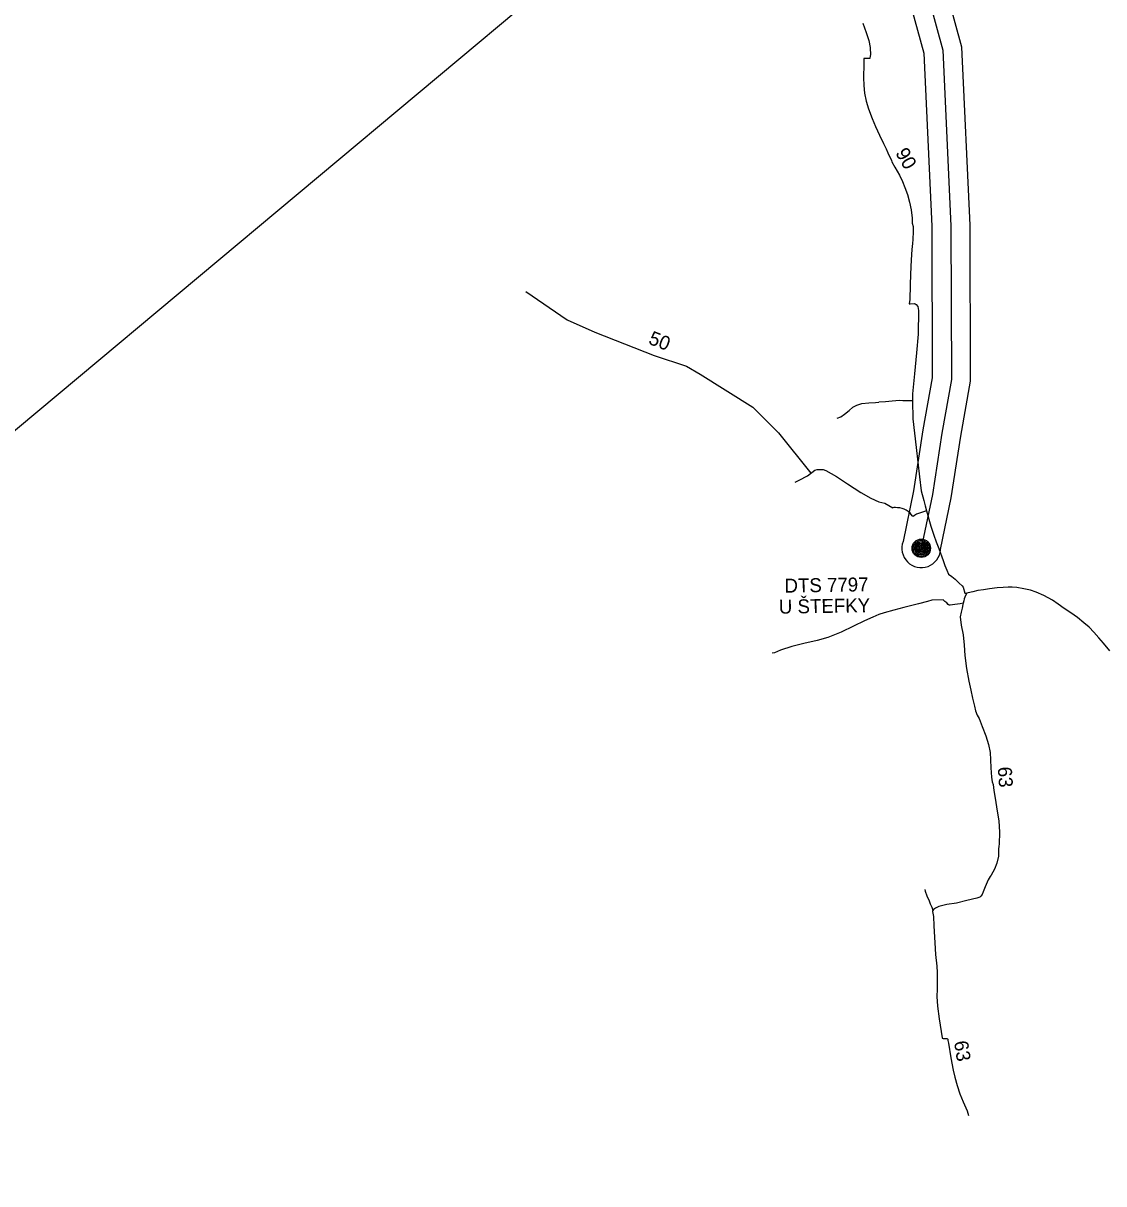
# Model space of a CAD drawing. Extents: x -444841 to -429545, y -1135312 to -1129851.
# Drawn here: x -443164 to -442545, y -1132368 to -1131703 of the extents above; entities that cross this region are included whole.
import ezdxf

# ---------------------------------------------------------------- set-up
doc = ezdxf.new("R2010")
doc.units = 0
for name, color, linetype in [('Vrstva 10', 7, 'Continuous'), ('Vrstva 11', 7, 'Continuous'), ('Vrstva 13', 7, 'Continuous'), ('Vrstva 15', 7, 'Continuous'), ('Vrstva 27', 7, 'Continuous'), ('Vrstva 30', 7, 'Continuous'), ('Vrstva 35', 7, 'Continuous'), ('Vrstva 38', 7, 'Continuous'), ('Vrstva 59', 7, 'Continuous')]:
    doc.layers.add(name, color=color, linetype=linetype)

msp = doc.modelspace()

# ---------------------------------------------------------------- linework, layer by layer
at = {"layer": 'Vrstva 10'}
msp.add_lwpolyline([(-442977.06, -1131273.28), (-442915.98, -1131331.48), (-442844.48, -1131404.21), (-442778.35, -1131472.42), (-442708.6, -1131543.25), (-442667.15, -1131610.03), (-442637.47, -1131718.34), (-442632.84, -1131818.91), (-442632.55, -1131906.97), (-442638.07, -1131937.77), (-442643.43, -1131972.89), (-442649.82, -1132003.75)], dxfattribs=at)
at = {"layer": 'Vrstva 11'}
for radius in [5.25, 4.55, 3.85, 3.15, 2.45, 1.75, 1.05, 0.35]:
    msp.add_circle((-442649.82, -1132003.75), radius, dxfattribs=at)
at = {"layer": 'Vrstva 15'}
for points in [[(-442638.75, -1132004.52), (-442632.6, -1131974.83), (-442627.22, -1131939.57), (-442621.55, -1131907.93), (-442621.84, -1131818.64), (-442626.54, -1131716.61), (-442656.97, -1131605.59), (-442699.9, -1131536.41), (-442770.48, -1131464.73), (-442836.6, -1131396.52), (-442908.26, -1131323.64), (-442958.88, -1131275.41)], [(-442977.76, -1131287.8), (-442923.69, -1131339.31), (-442852.35, -1131411.89), (-442786.22, -1131480.11), (-442717.3, -1131550.09), (-442677.34, -1131614.48), (-442648.4, -1131720.07), (-442643.84, -1131819.18), (-442643.56, -1131906.01), (-442648.92, -1131935.97), (-442654.27, -1131970.94), (-442660.2, -1131999.82)]]:
    msp.add_lwpolyline(points, dxfattribs=at)
msp.add_arc((-442649.82, -1132003.75), 11.1, 159.24982, 356.0105, dxfattribs=at)
at = {"layer": 'Vrstva 27'}
for points in [[(-442683.26, -1131702.79), (-442681.33, -1131708.2), (-442679.93, -1131712.74), (-442679.16, -1131716.75), (-442678.98, -1131721.16), (-442679.04, -1131721.49), (-442679.23, -1131723.11), (-442679.72, -1131723.11), (-442682.33, -1131723.08), (-442682.76, -1131723.14), (-442682.81, -1131727.48), (-442682.92, -1131732.83), (-442682.99, -1131733.98), (-442682.76, -1131738.59), (-442682.37, -1131742.94), (-442681.45, -1131747.48), (-442680.13, -1131751.94), (-442677.92, -1131757.48), (-442675.94, -1131762.15), (-442673.78, -1131766.98), (-442671.47, -1131771.89), (-442669.9, -1131774.96), (-442669, -1131777.08), (-442666.96, -1131781.5), (-442666.58, -1131782.26), (-442664.96, -1131785.47), (-442662.35, -1131789.93), (-442660.55, -1131793.61), (-442659.13, -1131796.94), (-442657.73, -1131801.12), (-442656.47, -1131805.53), (-442655.65, -1131809.8), (-442654.99, -1131814.57), (-442654.96, -1131817.48), (-442654.5, -1131819.47), (-442654.53, -1131822.31), (-442654.63, -1131826.82), (-442654.91, -1131829.09), (-442655.2, -1131832.5), (-442655.63, -1131838.52), (-442656.06, -1131846.7), (-442656.25, -1131852.95), (-442656.4, -1131861.27), (-442656.68, -1131863.73), (-442656.22, -1131863.72), (-442653.68, -1131863.56), (-442653.22, -1131863.67), (-442652.77, -1131864.06), (-442651.69, -1131865.23), (-442651.46, -1131867.54), (-442651.66, -1131881.03), (-442652.52, -1131891.73), (-442653.62, -1131903.77), (-442654.78, -1131915.3), (-442654.74, -1131919.22)], [(-442698.06, -1131929.23), (-442695.98, -1131928.4), (-442693.71, -1131926.88), (-442691.15, -1131924.8), (-442689.1, -1131922.92), (-442686.72, -1131921.67), (-442683.95, -1131920.76), (-442679.82, -1131920.37), (-442676.09, -1131920.27), (-442674.05, -1131920.13)], [(-442654.74, -1131919.22), (-442660.28, -1131919.2), (-442662.22, -1131919.17), (-442666.51, -1131919.48), (-442670.39, -1131919.87), (-442674.05, -1131920.13)], [(-442654.74, -1131919.22), (-442654.63, -1131929.58), (-442652.79, -1131946.11), (-442650.81, -1131962.76), (-442649.87, -1131970.86), (-442648.43, -1131976.41), (-442647.64, -1131979.49), (-442646.88, -1131982.38)], [(-442722, -1131965.95), (-442719.7, -1131964.73), (-442715.06, -1131962.27), (-442710.74, -1131958.98), (-442709.46, -1131958.66), (-442708.17, -1131958.54), (-442706.08, -1131958.67), (-442704.41, -1131959.25), (-442698.34, -1131962.72), (-442692.03, -1131966.75), (-442684.44, -1131971.71), (-442678.78, -1131975.11), (-442674.17, -1131977.14), (-442670.78, -1131977.87), (-442666.08, -1131980.59)], [(-442646.88, -1131982.38), (-442648.03, -1131982.66), (-442652.48, -1131984.22), (-442653.73, -1131984.96), (-442654.39, -1131985.48), (-442654.73, -1131985.4), (-442654.98, -1131985.1), (-442656.07, -1131983.91), (-442657.28, -1131982.65), (-442657.8, -1131982.3), (-442658.49, -1131981.9), (-442659.62, -1131981.43), (-442660.68, -1131980.9), (-442662.07, -1131980.66), (-442663.36, -1131980.52), (-442664.59, -1131980.46), (-442665.44, -1131980.46), (-442666.08, -1131980.59)], [(-442646.88, -1131982.38), (-442644.38, -1131991.12), (-442642.6, -1131996.33), (-442641.26, -1132000)], [(-442641.26, -1132000), (-442639.81, -1132003.98), (-442637.34, -1132010.82), (-442636.35, -1132013.66), (-442635.21, -1132016.3), (-442634.11, -1132018.53), (-442632.23, -1132019.94), (-442630.33, -1132021.55), (-442628, -1132023.81), (-442626.42, -1132025.2), (-442625.79, -1132026.04), (-442624.86, -1132029.46), (-442623.65, -1132029.44)], [(-442541.82, -1132062.57), (-442545.37, -1132058.16), (-442547.99, -1132055.08), (-442550.86, -1132051.8), (-442553.63, -1132049.05), (-442556.58, -1132046.46), (-442560.24, -1132043.5), (-442564.18, -1132040.75), (-442567.88, -1132038.25), (-442571.3, -1132035.8), (-442574.64, -1132033.55), (-442579.47, -1132030.9), (-442584, -1132028.88), (-442587.25, -1132027.83), (-442590.94, -1132026.94), (-442594.96, -1132026.31), (-442597.7, -1132026.1), (-442600.01, -1132025.96), (-442602.78, -1132026.32), (-442606.4, -1132026.51), (-442610.67, -1132027.06), (-442614.18, -1132027.62), (-442617.46, -1132028.05), (-442620.31, -1132028.72), (-442622.86, -1132029.24), (-442623.65, -1132029.44)], [(-442625.77, -1132035.29), (-442627.53, -1132035.66), (-442630.57, -1132036.07), (-442633.26, -1132036.43), (-442633.86, -1132036.38), (-442634.42, -1132036.06), (-442635.21, -1132034.98), (-442636.26, -1132034.2), (-442637.3, -1132033.25), (-442643.68, -1132033.56), (-442646.23, -1132034.22), (-442651.44, -1132035.61), (-442659.78, -1132037.74), (-442665.61, -1132039.32), (-442671.05, -1132040.66)], [(-442625.77, -1132035.29), (-442625.93, -1132036.04), (-442626.39, -1132038.05), (-442627.01, -1132040.31), (-442627.48, -1132043.06), (-442626.97, -1132047.91), (-442625.88, -1132053.42), (-442625.28, -1132059.22), (-442624.84, -1132065.27), (-442623.92, -1132072.58), (-442622.58, -1132080), (-442621.47, -1132085.06), (-442620.47, -1132089.63), (-442619.29, -1132094.27), (-442618.7, -1132096.98), (-442617.85, -1132099.45), (-442616.69, -1132101.36), (-442614.86, -1132105.84), (-442612.76, -1132111.32), (-442611.31, -1132116.14), (-442610.29, -1132120.69), (-442610.16, -1132124.96), (-442609.85, -1132129.62), (-442609.51, -1132134.86), (-442609.08, -1132137.55), (-442608.55, -1132139.14), (-442608.2, -1132142.61), (-442607.29, -1132148.15), (-442606.46, -1132153.25), (-442605.33, -1132159.95), (-442604.93, -1132166.37), (-442605.1, -1132173.36), (-442605.28, -1132174.53), (-442605.54, -1132176.17), (-442605.46, -1132177.95), (-442605.51, -1132180.25), (-442606.52, -1132184.11), (-442607.88, -1132187.57), (-442609.82, -1132191.03), (-442610.37, -1132191.83), (-442611.49, -1132193.82), (-442613.11, -1132197.7), (-442614.24, -1132200.67), (-442614.88, -1132202.15), (-442615.59, -1132203.15), (-442616.21, -1132203.72), (-442617.96, -1132204.17), (-442623.75, -1132205.54), (-442629.56, -1132207.04), (-442635.08, -1132207.86), (-442639.69, -1132209.08), (-442641.65, -1132209.94), (-442642.76, -1132210.74), (-442643.16, -1132211.29)], [(-442623.65, -1132029.44), (-442624.37, -1132030.91), (-442625.18, -1132032.69), (-442625.46, -1132033.89), (-442625.77, -1132035.29)], [(-442671.05, -1132040.66), (-442674.2, -1132041.7), (-442677.62, -1132043.15), (-442682.35, -1132045.4), (-442688.71, -1132048.44), (-442695.74, -1132051.81), (-442703.28, -1132054.87), (-442709.43, -1132056.59), (-442717.16, -1132058.28), (-442724.03, -1132059.96), (-442730.53, -1132062.13), (-442733.93, -1132063.61), (-442735.19, -1132063.8)], [(-442647.78, -1132199.24), (-442647.48, -1132200.22), (-442646.59, -1132202.97), (-442645.22, -1132205.82), (-442644.71, -1132207.56), (-442643.83, -1132209.39), (-442643.16, -1132211.29)], [(-442643.16, -1132211.29), (-442643.28, -1132211.88), (-442643.22, -1132212.94), (-442642.78, -1132214.75), (-442642.59, -1132220.1), (-442642.06, -1132229.81), (-442641.6, -1132236.62), (-442640.98, -1132243.29), (-442640.75, -1132246.78), (-442640.67, -1132256.31), (-442640.82, -1132260.57), (-442640.59, -1132266.21), (-442639.57, -1132273.37), (-442638.99, -1132277.01), (-442637.79, -1132284.19), (-442637.74, -1132284.49), (-442637.34, -1132284.72), (-442635.07, -1132284.6), (-442634.8, -1132284.77), (-442634.64, -1132285.12), (-442634.54, -1132285.82), (-442634.12, -1132287.34), (-442632.78, -1132295.82), (-442631.59, -1132302.83), (-442630.58, -1132306.85), (-442629.2, -1132311.68), (-442627.63, -1132316.45), (-442625.87, -1132320.94), (-442623.53, -1132326.18), (-442622.71, -1132328.71)]]:
    msp.add_lwpolyline(points, dxfattribs=at)
at = {"layer": 'Vrstva 35'}
msp.add_lwpolyline([(-442876.35, -1131856.53), (-442852.67, -1131872.82), (-442836.97, -1131879.92), (-442802.93, -1131893.25), (-442784.27, -1131899.46), (-442776.58, -1131903.91), (-442746.38, -1131922.85), (-442731.57, -1131937.66), (-442713.13, -1131960.8)], dxfattribs=at)
at = {"layer": 'Vrstva 59'}
msp.add_lwpolyline([(-441161.73, -1130257.99), (-444840.51, -1133333.5)], dxfattribs=at)

# ---------------------------------------------------------------- texts
at = {"layer": 'Vrstva 13'}
for s, p in [('DTS 7797', (-442728.13, -1132029.22)), ('U ŠTEFKY', (-442731.36, -1132041.28))]:
    msp.add_text(s, height=8, rotation=1, dxfattribs=at).set_placement(p)
at = {"layer": 'Vrstva 30'}
for s, rotation, p in [('90', 300.02305, (-442664.88, -1131777.19)), ('63', 273.80591, (-442605.97, -1132129.16)), ('63', 278.97957, (-442631.07, -1132286.53))]:
    msp.add_text(s, height=8, rotation=rotation, dxfattribs=at).set_placement(p)
at = {"layer": 'Vrstva 38'}
msp.add_text('50', height=8, rotation=338.62938, dxfattribs=at).set_placement((-442806.67, -1131886.41))

doc.saveas('drawing.dxf')
